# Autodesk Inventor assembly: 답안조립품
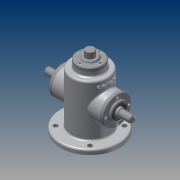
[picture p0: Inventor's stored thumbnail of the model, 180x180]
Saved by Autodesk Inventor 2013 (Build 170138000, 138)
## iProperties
Created: 2014-12
Part Number: 답안조립품
Document SubType Name: Assembly
Designer: CAD-B28
Author: CAD-B28
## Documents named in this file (12)
- C:\Users\CAD-B28\Desktop\441228V1004\답안조립품.iam
- C:\Users\CAD-B28\Desktop\441228V1004\본체.ipt
- C:\Users\CAD-B28\Desktop\441228V1004\커버.ipt
- C:\Users\CAD-B28\Desktop\441228V1004\베어링 6002.ipt
- 베어링 6002.ipt
- C:\Users\CAD-B28\Desktop\441228V1004\상단커버.ipt
- C:\Users\CAD-B28\Desktop\441228V1004\M3x0.5x8.ipt
- M3x0.5.ipt
- C:\Users\CAD-B28\Desktop\441228V1004\오일실.ipt
- 오일실.ipt
- C:\Users\CAD-B28\Desktop\441228V1004\편심축.ipt
- C:\Users\CAD-B28\Desktop\441228V1004\슬라이드.ipt
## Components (12 placed, 1 different names)
1. M3x0.5:2 — 각도:3
2. M3x0.5:4
3. M3x0.5:5
4. M3x0.5:6
5. M3x0.5:3 — 각도:2
6. M3x0.5:7
7. M3x0.5:8
8. M3x0.5:9
9. M3x0.5:1 — 각도:1
10. M3x0.5:10
11. M3x0.5:11
12. M3x0.5:12
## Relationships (3: Angle 3)
- 각도:1 [Angle]: M3x0.5:1
- 각도:2 [Angle]: M3x0.5:3
- 각도:3 [Angle]: M3x0.5:2
